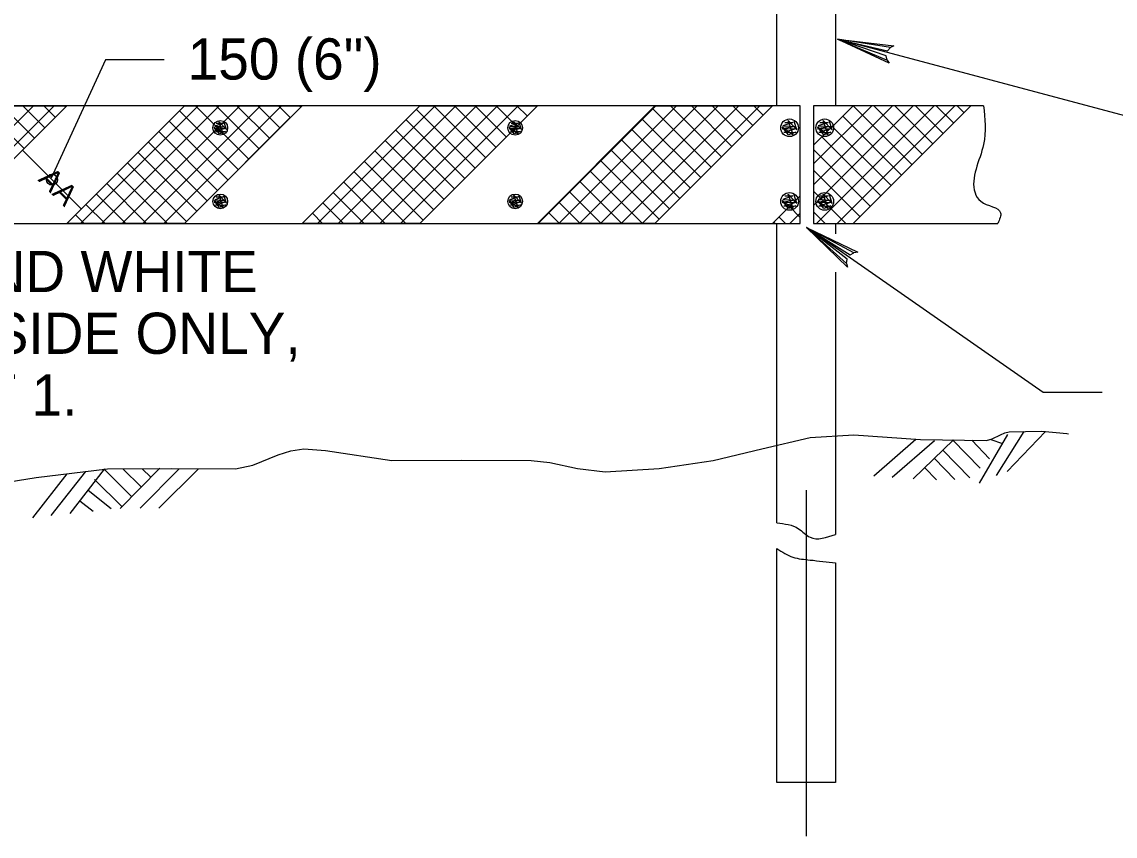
# Model space of a CAD drawing. Extents: x -4 to 901, y -468 to 720.
# Drawn here: x 180 to 269.2, y -67.8 to -1.4 of the extents above; entities that cross this region are included whole.
import ezdxf

# ---------------------------------------------------------------- set-up
doc = ezdxf.new("R2010")
doc.units = 0
doc.layers.add('2', color=7, linetype='Continuous')
doc.layers.add('3', color=7, linetype='Continuous')

msp = doc.modelspace()

# ---------------------------------------------------------------- linework, layer by layer
at = {"layer": '2'}
for p, q in [((283.5255, -12.651375), (246.5515, -2.816125)), ((243.5185, -8.236125), (111.99775, -8.236125)), ((174.05975, -17.836125), (183.65975, -8.236125)), ((174.05975, -17.836125), (183.65975, -8.236125)), ((183.65975, -17.836125), (193.25975, -8.236125)), ((183.65975, -17.836125), (193.25975, -8.236125)), ((193.25975, -17.836125), (202.85975, -8.236125)), ((193.25975, -17.836125), (202.85975, -8.236125)), ((202.85975, -17.836125), (212.45975, -8.236125)), ((202.85975, -17.836125), (212.45975, -8.236125)), ((212.45975, -17.836125), (222.05975, -8.236125)), ((212.45975, -17.836125), (222.05975, -8.236125)), ((222.05975, -17.836125), (231.65975, -8.236125)), ((222.05975, -17.836125), (231.65975, -8.236125)), ((231.65975, -17.836125), (241.25975, -8.236125)), ((231.65975, -17.836125), (241.25975, -8.236125)), ((243.5185, -17.836125), (243.5185, -8.236125)), ((244.604, -11.457875), (247.82575, -8.236125)), ((258.47175, -8.236125), (244.604, -8.236125)), ((244.604, -8.236125), (244.604, -17.836125)), ((247.82575, -17.836125), (257.42575, -8.236125)), ((247.82575, -17.836125), (257.42575, -8.236125)), ((196.41975, -9.664125), (195.72975, -9.898125)), ((195.85575, -9.664125), (196.41975, -9.664125)), ((196.43175, -10.522125), (196.08975, -9.538125)), ((196.08975, -9.538125), (196.68975, -10.180125)), ((196.68975, -10.180125), (196.50975, -9.598125)), ((201.84175, -9.256125), (198.22175, -12.874125)), ((201.84175, -9.256125), (198.22175, -12.874125)), ((220.48375, -9.664125), (219.79375, -9.898125)), ((219.91975, -9.664125), (220.48375, -9.664125)), ((220.49575, -10.522125), (220.15375, -9.538125)), ((220.15375, -9.538125), (220.75375, -10.180125)), ((220.75375, -10.180125), (220.57375, -9.598125)), ((242.92175, -9.590125), (242.09375, -9.872125)), ((242.24575, -9.590125), (242.92175, -9.590125)), ((242.93775, -10.620125), (242.52575, -9.440125)), ((242.52575, -9.440125), (243.24575, -10.210125)), ((243.24575, -10.210125), (243.02975, -9.512125)), ((245.79175, -9.590125), (244.96375, -9.872125)), ((245.11575, -9.590125), (245.79175, -9.590125)), ((245.80575, -10.620125), (245.39575, -9.440125)), ((245.39575, -9.440125), (246.11575, -10.210125)), ((246.11575, -10.210125), (245.89975, -9.512125)), ((196.57575, -9.946125), (195.68775, -10.114125)), ((196.11375, -10.522125), (195.68775, -9.976125)), ((195.68775, -9.976125), (196.43175, -10.522125)), ((195.68775, -10.114125), (196.67775, -10.078125)), ((195.72975, -9.898125), (196.57575, -9.946125)), ((196.67775, -10.078125), (195.79575, -10.348125)), ((195.79575, -10.348125), (196.61175, -10.330125)), ((196.61175, -10.330125), (196.11375, -10.522125)), ((196.18575, -10.036125), (196.18575, -10.036125)), ((196.18575, -10.036125), (196.18575, -10.036125)), ((220.63975, -9.946125), (219.75175, -10.114125)), ((220.17775, -10.522125), (219.75175, -9.976125)), ((219.75175, -9.976125), (220.49575, -10.522125)), ((219.75175, -10.114125), (220.74175, -10.078125)), ((219.79375, -9.898125), (220.63975, -9.946125)), ((220.74175, -10.078125), (219.85975, -10.348125)), ((219.85975, -10.348125), (220.67575, -10.330125)), ((220.67575, -10.330125), (220.17775, -10.522125)), ((220.24975, -10.036125), (220.24975, -10.036125)), ((220.24975, -10.036125), (220.24975, -10.036125)), ((243.10975, -9.928125), (242.04375, -10.130125)), ((242.55575, -10.620125), (242.04375, -9.964125)), ((242.04375, -9.964125), (242.93775, -10.620125)), ((242.04375, -10.130125), (243.23175, -10.088125)), ((242.09375, -9.872125), (243.10975, -9.928125)), ((243.23175, -10.088125), (242.17375, -10.412125)), ((242.17375, -10.412125), (243.15375, -10.390125)), ((243.15375, -10.390125), (242.55575, -10.620125)), ((242.64175, -10.036125), (242.64175, -10.036125)), ((242.64175, -10.036125), (242.64175, -10.036125)), ((245.97975, -9.928125), (244.91375, -10.130125)), ((245.42575, -10.620125), (244.91375, -9.964125)), ((244.91375, -9.964125), (245.80575, -10.620125)), ((244.91375, -10.130125), (246.10175, -10.088125)), ((244.96375, -9.872125), (245.97975, -9.928125)), ((246.10175, -10.088125), (245.04375, -10.412125)), ((245.04375, -10.412125), (246.02175, -10.390125)), ((246.02175, -10.390125), (245.42575, -10.620125)), ((245.51175, -10.036125), (245.51175, -10.036125)), ((184.83975, -16.656125), (180.03975, -11.856125)), ((184.83975, -16.656125), (180.03975, -11.856125)), ((187.44175, -14.056125), (183.82175, -17.674125)), ((187.44175, -14.056125), (183.82175, -17.674125)), ((196.57575, -15.946125), (195.68775, -16.114125)), ((196.11375, -16.522125), (195.68775, -15.976125)), ((195.68775, -15.976125), (196.43175, -16.522125)), ((196.41975, -15.664125), (195.72975, -15.898125)), ((195.72975, -15.898125), (196.57575, -15.946125)), ((195.85575, -15.664125), (196.41975, -15.664125)), ((196.43175, -16.522125), (196.08975, -15.538125)), ((196.08975, -15.538125), (196.68975, -16.180125)), ((196.18575, -16.036125), (196.18575, -16.036125)), ((196.18575, -16.036125), (196.18575, -16.036125)), ((196.68975, -16.180125), (196.50975, -15.598125)), ((220.63975, -15.946125), (219.75175, -16.114125)), ((220.17775, -16.522125), (219.75175, -15.976125)), ((219.75175, -15.976125), (220.49575, -16.522125)), ((220.48375, -15.664125), (219.79375, -15.898125)), ((219.79375, -15.898125), (220.63975, -15.946125)), ((219.91975, -15.664125), (220.48375, -15.664125)), ((220.49575, -16.522125), (220.15375, -15.538125)), ((220.15375, -15.538125), (220.75375, -16.180125)), ((220.24975, -16.036125), (220.24975, -16.036125)), ((220.24975, -16.036125), (220.24975, -16.036125)), ((220.75375, -16.180125), (220.57375, -15.598125)), ((241.25975, -17.836125), (243.5185, -15.577375)), ((243.10975, -15.928125), (242.04375, -16.130125)), ((242.55575, -16.620125), (242.04375, -15.964125)), ((242.04375, -15.964125), (242.93775, -16.620125)), ((242.92175, -15.590125), (242.09375, -15.872125)), ((242.09375, -15.872125), (243.10975, -15.928125)), ((242.24575, -15.590125), (242.92175, -15.590125)), ((242.93775, -16.620125), (242.52575, -15.440125)), ((242.52575, -15.440125), (243.24575, -16.210125)), ((242.64175, -16.036125), (242.64175, -16.036125)), ((242.64175, -16.036125), (242.64175, -16.036125)), ((243.24575, -16.210125), (243.02975, -15.512125)), ((245.97975, -15.928125), (244.91375, -16.130125)), ((245.42575, -16.620125), (244.91375, -15.964125)), ((244.91375, -15.964125), (245.80575, -16.620125)), ((245.79175, -15.590125), (244.96375, -15.872125)), ((244.96375, -15.872125), (245.97975, -15.928125)), ((245.11575, -15.590125), (245.79175, -15.590125)), ((245.80575, -16.620125), (245.39575, -15.440125)), ((245.39575, -15.440125), (246.11575, -16.210125)), ((245.51175, -16.036125), (245.51175, -16.036125)), ((246.11575, -16.210125), (245.89975, -15.512125)), ((195.68775, -16.114125), (196.67775, -16.078125)), ((196.67775, -16.078125), (195.79575, -16.348125)), ((195.79575, -16.348125), (196.61175, -16.330125)), ((196.61175, -16.330125), (196.11375, -16.522125)), ((219.75175, -16.114125), (220.74175, -16.078125)), ((220.74175, -16.078125), (219.85975, -16.348125)), ((219.85975, -16.348125), (220.67575, -16.330125)), ((220.67575, -16.330125), (220.17775, -16.522125)), ((242.04375, -16.130125), (243.23175, -16.088125)), ((243.23175, -16.088125), (242.17375, -16.412125)), ((242.17375, -16.412125), (243.15375, -16.390125)), ((243.15375, -16.390125), (242.55575, -16.620125)), ((244.91375, -16.130125), (246.10175, -16.088125)), ((246.10175, -16.088125), (245.04375, -16.412125)), ((245.04375, -16.412125), (246.02175, -16.390125)), ((246.02175, -16.390125), (245.42575, -16.620125)), ((111.99775, -17.836125), (243.5185, -17.836125)), ((244.604, -17.836125), (259.63175, -17.836125)), ((263.34375, -31.628125), (244.03375, -18.162125)), ((268.14375, -31.628125), (263.34375, -31.628125)), ((260.40975, -38.070125), (263.52175, -34.790125)), ((249.51175, -38.414125), (252.94575, -35.436125)), ((251.01175, -38.520125), (254.46375, -35.526125)), ((252.73975, -38.668125), (256.02175, -35.488125)), ((255.95175, -35.486125), (258.19575, -37.802125)), ((257.50575, -35.510125), (258.96975, -37.020125)), ((258.15175, -39.024125), (260.44775, -35.044125)), ((259.07375, -35.454125), (260.02375, -35.776125)), ((259.54175, -38.384125), (261.78225, -34.801875)), ((255.16175, -36.322125), (257.35575, -38.584125)), ((254.45975, -37.002125), (256.12575, -38.722125)), ((180.89375, -41.842125), (183.69775, -38.266125)), ((182.38575, -41.662125), (185.20575, -38.066125)), ((183.92975, -41.474125), (186.74975, -37.878125)), ((186.67975, -37.852125), (188.97575, -40.118125)), ((188.01375, -41.076125), (191.23975, -37.804125)), ((188.23375, -37.842125), (189.72975, -39.318125)), ((189.65575, -41.064125), (192.83175, -37.846125)), ((189.80575, -37.832125), (190.51975, -38.536125)), ((191.16575, -41.040125), (194.38575, -37.864125)), ((253.66975, -37.766125), (254.62175, -38.750125)), ((185.90775, -38.704125), (188.15175, -40.918125)), ((185.40775, -39.590125), (187.29375, -41.068125)), ((243.99775, -39.574125), (243.99775, -67.796125)), ((184.72975, -40.456125), (185.80575, -41.300125))]:
    msp.add_line(p, q, dxfattribs=at)
for points in [[(241.59775, -8.236125), (241.59775, 1.363875)], [(246.39775, 1.363875), (246.39775, -8.236125)], [(250.60075, -4.521875), (250.52875, -4.173125), (246.5515, -2.816125), (250.60075, -4.521875), (250.7635, -4.766375), (246.5515, -2.816125), (250.64475, -3.749625), (250.8765, -3.490875), (246.5515, -2.816125), (251.16, -3.354875), (250.8765, -3.490875)], [(191.60775, -4.490125), (186.80775, -4.490125), (182.39575, -14.154125)], [(171.33975, -17.836125), (180.93975, -8.236125)], [(173.03575, -17.836125), (182.63575, -8.236125)], [(180.17175, -11.726125), (176.68375, -8.236125)], [(181.01975, -10.876125), (178.37975, -8.236125)], [(181.86775, -10.028125), (180.07775, -8.236125)], [(182.71575, -9.180125), (181.77375, -8.236125)], [(183.56575, -8.332125), (183.47175, -8.236125)], [(184.78775, -17.836125), (194.38775, -8.236125)], [(186.48375, -17.836125), (196.08375, -8.238125)], [(188.18175, -17.836125), (197.78175, -8.236125)], [(189.87775, -17.836125), (199.47775, -8.236125)], [(191.57575, -17.836125), (201.17575, -8.236125)], [(197.65775, -13.438125), (192.85775, -8.638125)], [(198.50575, -12.590125), (194.15375, -8.236125)], [(199.35375, -11.742125), (195.84975, -8.236125)], [(200.20375, -10.892125), (197.54775, -8.236125)], [(201.05175, -10.044125), (199.24375, -8.236125)], [(201.89975, -9.196125), (200.94175, -8.236125)], [(202.74975, -8.348125), (202.63775, -8.236125)], [(204.11175, -17.836125), (213.71175, -8.236125)], [(205.80975, -17.836125), (215.40975, -8.236125)], [(207.50575, -17.836125), (217.10575, -8.236125)], [(209.20375, -17.836125), (218.80375, -8.236125)], [(210.89975, -17.836125), (220.49975, -8.236125)], [(216.98375, -13.314125), (212.18375, -8.514125)], [(217.83175, -12.464125), (213.60375, -8.236125)], [(218.67975, -11.616125), (215.30175, -8.236125)], [(219.52775, -10.768125), (216.99775, -8.236125)], [(220.37775, -9.920125), (218.69575, -8.236125)], [(221.22575, -9.070125), (220.39175, -8.236125)], [(222.11775, -17.836125), (231.71775, -8.236125)], [(223.81575, -17.836125), (233.41575, -8.236125)], [(225.51175, -17.836125), (235.11175, -8.236125)], [(227.20975, -17.836125), (236.80975, -8.236125)], [(228.90575, -17.836125), (238.50575, -8.236125)], [(230.60375, -17.836125), (240.20375, -8.236125)], [(236.24575, -13.250125), (231.44575, -8.450125)], [(237.09375, -12.402125), (232.92975, -8.236125)], [(237.94375, -11.552125), (234.62775, -8.236125)], [(238.79175, -10.704125), (236.32375, -8.236125)], [(239.63975, -9.856125), (238.02175, -8.236125)], [(240.48975, -9.008125), (239.71775, -8.236125)], [(244.604, -16.375875), (252.74175, -8.236125)], [(244.604, -14.677875), (251.04575, -8.236125)], [(244.604, -12.981875), (249.34775, -8.236125)], [(244.83975, -17.836125), (254.43975, -8.236125)], [(246.53775, -17.836125), (256.13575, -8.236125)], [(252.62575, -13.036125), (247.82575, -8.236125), (247.82575, -8.236125)], [(253.47375, -12.188125), (249.52375, -8.236125)], [(254.32175, -11.340125), (251.21975, -8.236125)], [(255.17175, -10.492125), (252.91775, -8.236125)], [(256.01975, -9.642125), (254.61375, -8.236125)], [(256.86775, -8.794125), (256.31175, -8.236125)], [(196.80975, -14.288125), (192.00975, -9.488125)], [(216.13375, -14.162125), (211.33375, -9.362125)], [(235.39775, -14.098125), (230.59775, -9.298125)], [(251.77775, -13.886125), (246.97775, -9.086125)], [(195.95975, -15.136125), (191.15975, -10.336125)], [(215.28575, -15.010125), (210.48575, -10.210125)], [(234.54975, -14.946125), (229.74975, -10.148125)], [(250.92775, -14.734125), (246.12775, -9.934125)], [(195.11175, -15.984125), (190.31175, -11.184125)], [(214.43775, -15.858125), (209.63775, -11.058125)], [(233.69975, -15.796125), (228.89975, -10.996125)], [(250.07975, -15.582125), (245.27975, -10.782125)], [(194.26375, -16.832125), (189.46375, -12.032125)], [(213.58975, -16.708125), (208.78975, -11.908125)], [(232.85175, -16.644125), (228.05175, -11.844125)], [(249.23175, -16.430125), (244.604, -11.804375)], [(193.41575, -17.682125), (188.61575, -12.882125)], [(212.73975, -17.556125), (207.93975, -12.756125)], [(232.00375, -17.492125), (227.20375, -12.692125)], [(191.87375, -17.836125), (187.76575, -13.730125)], [(211.32375, -17.836125), (207.09175, -13.604125)], [(230.64975, -17.836125), (226.35575, -13.542125)], [(248.38375, -17.280125), (244.604, -13.500375)], [(190.17575, -17.836125), (186.91775, -14.578125)], [(209.62775, -17.836125), (206.24375, -14.452125)], [(228.95375, -17.836125), (225.50575, -14.390125)], [(188.47975, -17.836125), (186.06975, -15.426125)], [(207.92975, -17.836125), (205.39575, -15.302125)], [(227.25575, -17.836125), (224.65775, -15.238125)], [(247.24375, -17.836125), (244.604, -15.198125)], [(186.78175, -17.836125), (185.22175, -16.276125)], [(206.23375, -17.836125), (204.54575, -16.150125)], [(223.86175, -17.836125), (222.96175, -16.936125)], [(225.55975, -17.836125), (223.80975, -16.086125)], [(243.5185, -17.349125), (242.63175, -16.464125), (242.63175, -16.464125)], [(245.54575, -17.836125), (244.604, -16.894375)], [(185.08575, -17.836125), (184.37175, -17.124125)], [(204.53575, -17.836125), (203.69775, -16.998125)], [(222.16575, -17.836125), (222.11175, -17.784125)], [(241.45975, -17.836125), (241.35975, -17.736125), (241.35975, -17.736125)], [(241.59775, -42.262125), (241.59775, -17.836125)], [(242.30975, -17.836125), (241.78375, -17.312125), (241.78375, -17.312125)], [(242.67175, -17.836125), (243.5185, -16.989375)], [(246.39775, -17.836125), (246.39775, -18.685125)], [(247.29775, -21.104125), (247.34375, -20.752125), (244.03375, -18.162125), (247.29775, -21.104125), (247.36975, -21.388125), (244.03375, -18.162125), (247.59175, -20.390125), (247.89575, -20.222125), (244.03375, -18.162125), (248.20975, -20.186125), (247.89575, -20.222125)], [(246.39775, -21.814125), (246.39775, -43.190125)], [(175.36975, -39.476125), (181.15975, -38.556125), (186.97575, -37.850125), (192.20175, -37.816125), (197.42175, -37.850125), (198.83175, -37.540125), (200.89575, -36.704125), (201.93375, -36.364125), (202.99175, -36.226125), (204.78375, -36.360125), (210.18775, -37.154125), (215.88175, -37.132125), (221.56375, -37.154125), (223.07575, -37.340125), (225.33575, -37.806125), (227.59775, -38.082125), (232.00775, -37.818125), (236.41975, -37.154125), (240.37575, -36.224125), (244.31175, -35.298125), (247.88575, -35.060125), (253.33375, -35.446125), (258.70375, -35.530125), (259.17775, -35.402125), (259.86775, -35.062125), (260.21175, -34.914125), (260.55975, -34.834125), (263.22175, -34.764125), (265.27575, -34.960125), (265.39975, -34.992125)], [(246.39775, -45.512125), (246.39775, -63.436125), (241.59775, -63.436125), (241.59775, -44.350125)]]:
    msp.add_lwpolyline(points, dxfattribs=at)
for points in [[(164.45975, -17.836125), (174.05975, -8.236125), (183.65975, -8.236125), (174.05975, -17.836125)], [(183.65975, -17.836125), (193.25975, -8.236125), (202.85975, -8.236125), (193.25975, -17.836125)], [(202.85975, -17.836125), (212.45975, -8.236125), (222.05975, -8.236125), (212.45975, -17.836125)], [(222.05975, -17.836125), (231.65975, -8.236125), (241.25975, -8.236125), (231.65975, -17.836125)]]:
    msp.add_lwpolyline(points, close=True, dxfattribs=at)
for centre, radius in [((196.18605, -10.037028), 0.6), ((220.24893, -10.037028), 0.6), ((242.64189, -10.037028), 0.72), ((245.51157, -10.037028), 0.72), ((182.45301, -14.267268), 0.455664), ((182.45301, -14.267268), 0.455664), ((196.18605, -16.037028), 0.6), ((220.24893, -16.037028), 0.6), ((242.64189, -16.037028), 0.72), ((245.51157, -16.037028), 0.72)]:
    msp.add_circle(centre, radius, dxfattribs=at)
for points in [[(258.47175, -8.236125), (258.47175, -11.388125), (257.77575, -15.334125), (258.23975, -16.030125), (259.86375, -16.960125), (259.63175, -17.836125)], [(258.47175, -8.236125), (258.47175, -11.388125), (257.77575, -15.334125), (258.23975, -16.030125), (259.86375, -16.960125), (259.63175, -17.836125)], [(241.59775, -42.262125), (243.38375, -42.726125), (244.31175, -43.422125), (246.39775, -43.190125)], [(241.59775, -44.350125), (242.91775, -45.046125), (244.31175, -45.280125), (246.39775, -45.512125)]]:
    msp.add_spline(points, degree=3, dxfattribs=at)

# ---------------------------------------------------------------- texts
for p in [(181.26175, -14.300125), (181.26175, -14.300125), (182.39575, -15.434125), (182.39575, -15.434125)]:
    msp.add_text('A', height=1.727988, rotation=315.00375278, dxfattribs=at).set_placement(p)
at = {"layer": '3'}
for s, height, p in [('150 (6")', 3.36, (193.5185, -6.101375)), ('ALTERNATE RED AND WHITE', 3.359988, (135.59175, -23.430125)), ('STRIPES, TRAFFIC SIDE ONLY,', 3.359988, (135.59175, -28.470125)), ('SEE NOTE 1, SHEET 1.', 3.359988, (135.59175, -33.510125))]:
    msp.add_text(s, height=height, dxfattribs=at).set_placement(p)

doc.saveas('drawing.dxf')
